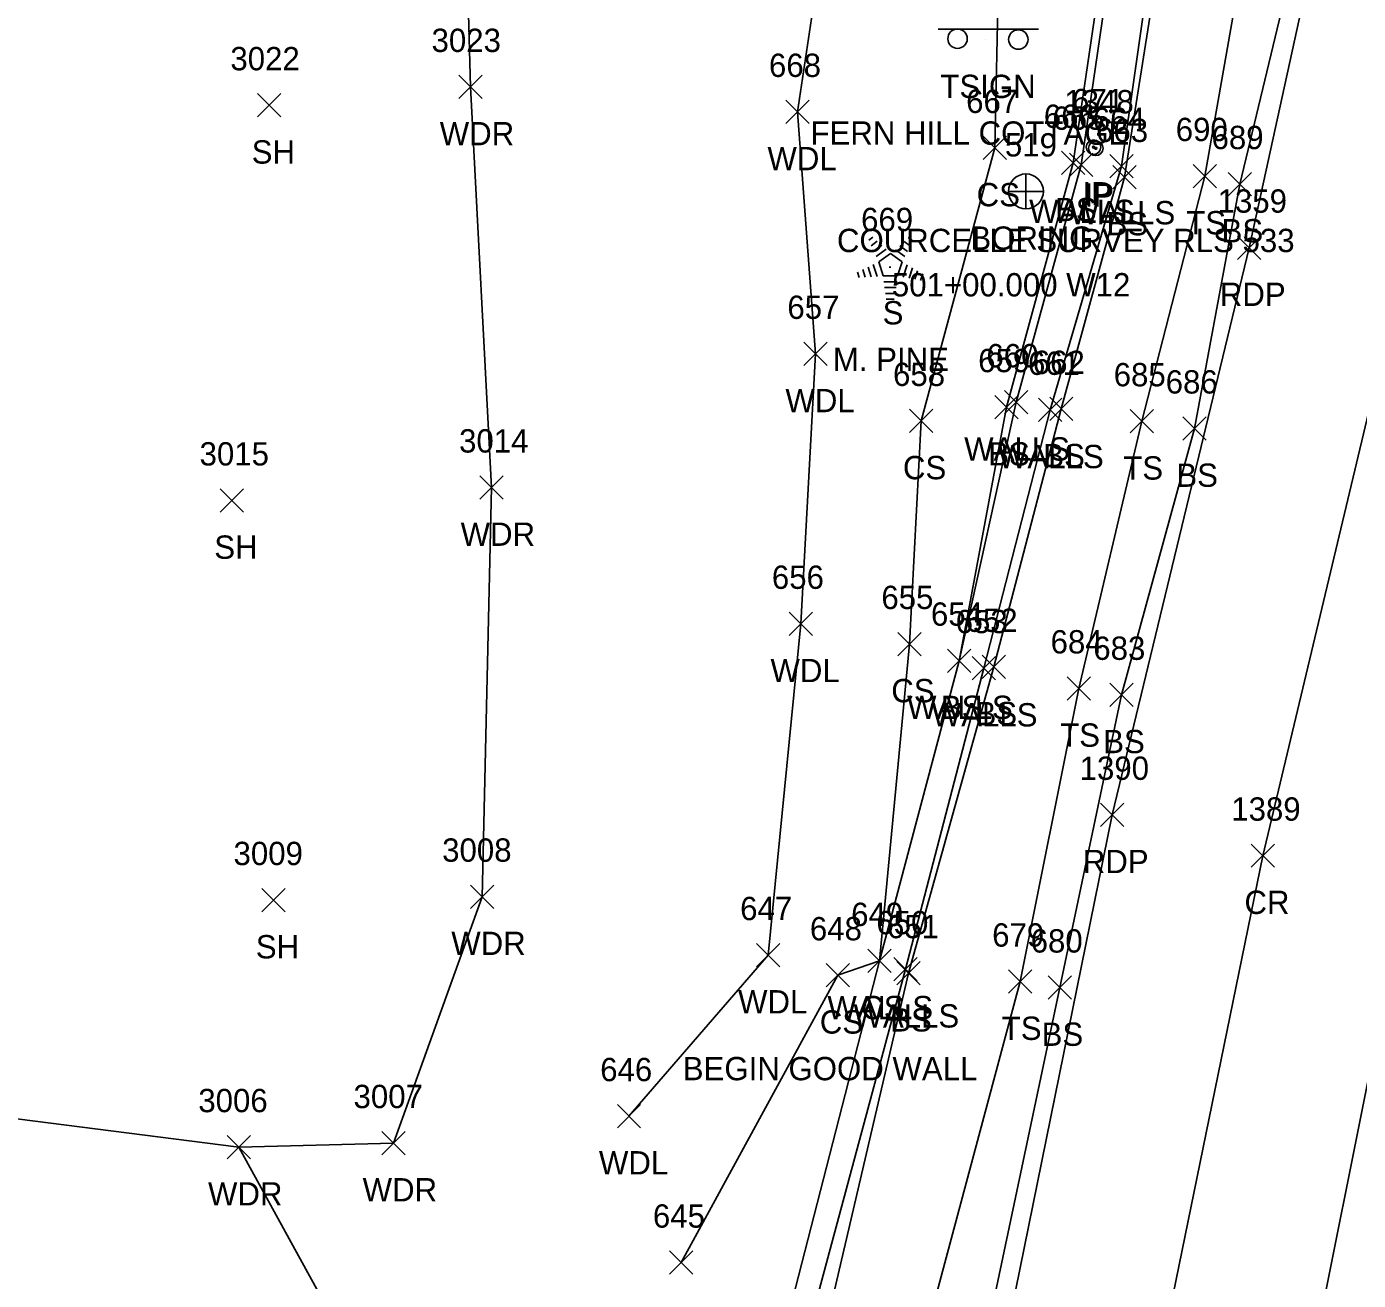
# Model space of a CAD drawing. Extents: x 1509053 to 1511576, y 400838 to 402572.
# Drawn here: x 1509675.3 to 1509789.5, y 401477.9 to 401585.4 of the extents above; entities that cross this region are included whole.
import ezdxf

# ---------------------------------------------------------------- set-up
doc = ezdxf.new("R2010")
doc.units = 0
for name, color, linetype in [('G_A', 7, 'Continuous'), ('G_C', 7, 'Continuous'), ('G_I', 7, 'Continuous'), ('GA_P', 7, 'Continuous'), ('L_A', 7, 'Continuous'), ('L_C', 7, 'Continuous'), ('L_I', 7, 'Continuous'), ('L_TIC', 7, 'Continuous'), ('LAWA', 7, 'Continuous'), ('LELB', 7, 'Continuous'), ('LSOGP', 7, 'Continuous'), ('LTC', 7, 'Continuous'), ('LWS', 7, 'Continuous'), ('M_A', 7, 'Continuous'), ('M_C', 7, 'Continuous'), ('M_I', 7, 'Continuous'), ('MPIR', 7, 'Continuous'), ('P_A', 7, 'Continuous'), ('P_I', 7, 'Continuous'), ('P_TIC', 7, 'Continuous'), ('PET', 7, 'Continuous'), ('PRC', 7, 'Continuous'), ('S_A', 7, 'Continuous'), ('S_C', 7, 'Continuous'), ('SSGN', 7, 'Continuous')]:
    doc.layers.add(name, color=color, linetype=linetype)

msp = doc.modelspace()

# ---------------------------------------------------------------- linework, layer by layer
at = {"layer": 'GA_P'}
for p, q in [((1509760.96, 401571.27), (1509760.96, 401572.77)), ((1509760.96, 401571.27), (1509759.46, 401571.27)), ((1509762.46, 401571.27), (1509760.96, 401571.27)), ((1509760.96, 401569.77), (1509760.96, 401571.27))]:
    msp.add_line(p, q, dxfattribs=at)
for start, end in [(90, 180), (0, 90), (180, 270), (270, 0)]:
    msp.add_arc((1509760.96, 401571.27), 1.5, start, end, dxfattribs=at)
at = {"layer": 'L_TIC'}
for points in [[(1509712.34, 401579.23), (1509714.34, 401581.23)], [(1509714.34, 401579.23), (1509712.34, 401581.23)], [(1509695.09, 401577.66), (1509697.09, 401579.66)], [(1509697.09, 401577.66), (1509695.09, 401579.66)], [(1509740.39, 401577.09), (1509742.39, 401579.09)], [(1509742.39, 401577.09), (1509740.39, 401579.09)], [(1509757.3, 401574), (1509759.3, 401576)], [(1509759.3, 401574), (1509757.3, 401576)], [(1509764.02, 401572.72), (1509766.02, 401574.72)], [(1509766.02, 401572.72), (1509764.02, 401574.72)], [(1509764.7, 401572.56), (1509766.7, 401574.56)], [(1509766.7, 401572.56), (1509764.7, 401574.56)], [(1509768.16, 401572.45), (1509770.16, 401574.45)], [(1509770.16, 401572.45), (1509768.16, 401574.45)], [(1509768.43, 401571.51), (1509770.43, 401573.51)], [(1509770.43, 401571.51), (1509768.43, 401573.51)], [(1509775.3, 401571.59), (1509777.3, 401573.59)], [(1509777.3, 401571.59), (1509775.3, 401573.59)], [(1509778.3, 401570.9), (1509780.3, 401572.9)], [(1509780.3, 401570.9), (1509778.3, 401572.9)], [(1509741.92, 401556.34), (1509743.92, 401558.34)], [(1509743.92, 401556.34), (1509741.92, 401558.34)], [(1509758.29, 401551.77), (1509760.29, 401553.77)], [(1509760.29, 401551.77), (1509758.29, 401553.77)], [(1509759.12, 401552.19), (1509761.12, 401554.19)], [(1509761.12, 401552.19), (1509759.12, 401554.19)], [(1509762.03, 401551.54), (1509764.03, 401553.54)], [(1509764.03, 401551.54), (1509762.03, 401553.54)], [(1509763, 401551.62), (1509765, 401553.62)], [(1509765, 401551.62), (1509763, 401553.62)], [(1509750.98, 401550.59), (1509752.98, 401552.59)], [(1509752.98, 401550.59), (1509750.98, 401552.59)], [(1509769.9, 401550.56), (1509771.9, 401552.56)], [(1509771.9, 401550.56), (1509769.9, 401552.56)], [(1509774.42, 401549.94), (1509776.42, 401551.94)], [(1509776.42, 401549.94), (1509774.42, 401551.94)], [(1509714.13, 401544.88), (1509716.13, 401546.88)], [(1509716.13, 401544.88), (1509714.13, 401546.88)], [(1509691.88, 401543.77), (1509693.88, 401545.77)], [(1509693.88, 401543.77), (1509691.88, 401545.77)], [(1509740.65, 401533.19), (1509742.65, 401535.19)], [(1509742.65, 401533.19), (1509740.65, 401535.19)], [(1509749.98, 401531.46), (1509751.98, 401533.46)], [(1509751.98, 401531.46), (1509749.98, 401533.46)], [(1509754.23, 401530.03), (1509756.23, 401532.03)], [(1509756.23, 401530.03), (1509754.23, 401532.03)], [(1509754.23, 401530.03), (1509756.23, 401532.03)], [(1509756.23, 401530.03), (1509754.23, 401532.03)], [(1509756.35, 401529.39), (1509758.35, 401531.39)], [(1509758.35, 401529.39), (1509756.35, 401531.39)], [(1509757.2, 401529.5), (1509759.2, 401531.5)], [(1509759.2, 401529.5), (1509757.2, 401531.5)], [(1509764.49, 401527.65), (1509766.49, 401529.65)], [(1509766.49, 401527.65), (1509764.49, 401529.65)], [(1509768.15, 401527.1), (1509770.15, 401529.1)], [(1509770.15, 401527.1), (1509768.15, 401529.1)], [(1509695.44, 401509.5), (1509697.44, 401511.5)], [(1509697.44, 401509.5), (1509695.44, 401511.5)], [(1509713.33, 401509.79), (1509715.33, 401511.79)], [(1509715.33, 401509.79), (1509713.33, 401511.79)], [(1509737.87, 401504.78), (1509739.87, 401506.78)], [(1509739.87, 401504.78), (1509737.87, 401506.78)], [(1509747.4, 401504.28), (1509749.4, 401506.28)], [(1509749.4, 401504.28), (1509747.4, 401506.28)], [(1509747.4, 401504.28), (1509749.4, 401506.28)], [(1509749.4, 401504.28), (1509747.4, 401506.28)], [(1509749.64, 401503.57), (1509751.64, 401505.57)], [(1509751.64, 401503.57), (1509749.64, 401505.57)], [(1509743.85, 401503.05), (1509745.85, 401505.05)], [(1509745.85, 401503.05), (1509743.85, 401505.05)], [(1509749.89, 401503.23), (1509751.89, 401505.23)], [(1509751.89, 401503.23), (1509749.89, 401505.23)], [(1509759.48, 401502.51), (1509761.48, 401504.51)], [(1509761.48, 401502.51), (1509759.48, 401504.51)], [(1509762.87, 401502), (1509764.87, 401504)], [(1509764.87, 401502), (1509762.87, 401504)], [(1509725.93, 401490.97), (1509727.93, 401492.97)], [(1509727.93, 401490.97), (1509725.93, 401492.97)], [(1509705.73, 401488.66), (1509707.73, 401490.66)], [(1509707.73, 401488.66), (1509705.73, 401490.66)], [(1509692.47, 401488.31), (1509694.47, 401490.31)], [(1509694.47, 401488.31), (1509692.47, 401490.31)], [(1509730.39, 401478.41), (1509732.39, 401480.41)], [(1509732.39, 401478.41), (1509730.39, 401480.41)]]:
    msp.add_lwpolyline(points, dxfattribs=at)
at = {"layer": 'LAWA'}
for points in [[(1509638.88, 401488.13), (1509666.35, 401492.77), (1509693.47, 401489.31), (1509706.73, 401489.66), (1509714.33, 401510.79), (1509715.13, 401545.88), (1509713.34, 401580.23), (1509712.38, 401615.78), (1509710.87, 401643.63), (1509696.77, 401674.88), (1509690.26, 401693.05), (1509667.45, 401720.56), (1509662.48, 401743.44), (1509649.82, 401764.29), (1509628.65, 401784.18), (1509611.29, 401798.2), (1509592.85, 401815.68), (1509576.11, 401831.25), (1509568.72, 401841.78), (1509569.85, 401855.18), (1509582.24, 401868.06), (1509599.14, 401876.59), (1509619.4, 401883.23)], [(1509726.93, 401491.97), (1509738.87, 401505.78), (1509741.65, 401534.19), (1509742.92, 401557.34), (1509741.39, 401578.09), (1509745.24, 401603.86), (1509743.92, 401621.55), (1509740.79, 401647.31), (1509747.4, 401658.17), (1509733.89, 401672.71)]]:
    msp.add_lwpolyline(points, dxfattribs=at)
at = {"layer": 'LELB'}
for points in [[(1509755.23, 401531.03), (1509759.29, 401552.77), (1509765.02, 401573.72), (1509768.89, 401600.17), (1509768.39, 401615.04), (1509767.46, 401619.69), (1509766.78, 401624.18), (1509765.92, 401630.49), (1509768.74, 401634.34), (1509769.29, 401651.82), (1509765.23, 401681.64), (1509759.03, 401705.77), (1509750.68, 401722.86), (1509752.06, 401726.1), (1509747.7, 401751.42), (1509733.73, 401785.72), (1509720.36, 401816.7), (1509711.77, 401831.6), (1509702.38, 401845.68), (1509682.87, 401874.27), (1509678.54, 401880.58), (1509678.34, 401883.46)], [(1509731.39, 401479.41), (1509744.85, 401504.05), (1509748.4, 401505.28), (1509750.98, 401532.46), (1509751.98, 401551.59), (1509758.3, 401575), (1509758.92, 401604.42), (1509759.53, 401620.15), (1509759.5, 401642.39), (1509763.87, 401657.52), (1509763.43, 401681.67), (1509755.33, 401705.43), (1509747.09, 401724.92), (1509745.86, 401750.35), (1509730.75, 401785.27), (1509718.16, 401815.85), (1509711.77, 401831.6), (1509699.84, 401843.77), (1509676.05, 401879.71), (1509667.99, 401880.98)], [(1509747.77, 401416.63), (1509750.21, 401428.63), (1509752.14, 401443.01), (1509750.46, 401466.15), (1509760.48, 401503.51), (1509765.49, 401528.65), (1509770.9, 401551.56), (1509776.3, 401572.59), (1509780.48, 401596.32), (1509778.93, 401605.73), (1509782.51, 401627.45), (1509784.95, 401662.22), (1509781.8, 401680.58), (1509772.99, 401719.38), (1509769.17, 401721), (1509769.65, 401723.75), (1509771.91, 401724.32), (1509762.66, 401754.93), (1509756.13, 401775.54), (1509751.07, 401789.41), (1509736.27, 401824.32), (1509727.62, 401840.87), (1509712.26, 401861.01), (1509694.01, 401878.11)], [(1509745.54, 401417.2), (1509747.58, 401428.44), (1509752.14, 401443.01), (1509755.83, 401464.96), (1509763.87, 401503), (1509769.15, 401528.1), (1509775.42, 401550.94), (1509779.3, 401571.9), (1509785.18, 401596.41), (1509784.53, 401607.91), (1509782.51, 401627.45), (1509780.91, 401662.72), (1509779.34, 401679.41)], [(1509718.39, 401429.02), (1509722.72, 401429.03), (1509731.91, 401425.72), (1509733.42, 401429.22), (1509734.23, 401430.09), (1509736.1, 401435.75), (1509737.32, 401446.05), (1509750.89, 401504.23), (1509758.2, 401530.5), (1509764, 401552.62), (1509769.43, 401572.51), (1509773.58, 401598.87), (1509773.31, 401621.52)]]:
    msp.add_lwpolyline(points, dxfattribs=at)
at = {"layer": 'LSOGP'}
msp.add_lwpolyline([(1509619.06, 401604.82), (1509615.52, 401571.4), (1509614.57, 401540.12), (1509638.88, 401488.13), (1509666.35, 401492.77), (1509693.47, 401489.31), (1509718.05, 401444.54), (1509718.3, 401438.26), (1509718.5, 401437.3), (1509717.88, 401435.11), (1509718.83, 401433.96), (1509718.39, 401429.02), (1509705.02, 401423.16)], dxfattribs=at)
at = {"layer": 'LTC'}
for p, q in [((1509747.49, 401567.08), (1509747.84, 401567.34)), ((1509747.7, 401566.61), (1509748.22, 401567)), ((1509750.51, 401566.97), (1509751.06, 401566.57)), ((1509750.88, 401567.32), (1509751.3, 401567.01)), ((1509747.9, 401566.15), (1509748.61, 401566.66)), ((1509748.11, 401565.68), (1509748.99, 401566.32)), ((1509748.34, 401565.23), (1509749.35, 401565.96)), ((1509749.35, 401565.96), (1509750.35, 401565.24)), ((1509749.77, 401566.27), (1509750.58, 401565.69)), ((1509750.14, 401566.62), (1509750.82, 401566.13)), ((1509747.43, 401564.79), (1509747.7, 401563.96)), ((1509747.88, 401565.01), (1509748.22, 401563.99)), ((1509748.34, 401565.23), (1509748.73, 401564.03)), ((1509750.35, 401565.24), (1509749.96, 401564.03)), ((1509750.79, 401564.97), (1509750.45, 401563.93)), ((1509751.23, 401564.72), (1509750.94, 401563.83)), ((1509746.52, 401564.36), (1509746.67, 401563.89)), ((1509746.97, 401564.57), (1509747.19, 401563.92)), ((1509749.96, 401564.03), (1509748.73, 401564.03)), ((1509749.92, 401563.53), (1509748.77, 401563.53)), ((1509751.67, 401564.47), (1509751.44, 401563.74)), ((1509752.12, 401564.21), (1509751.93, 401563.64)), ((1509749.83, 401563.03), (1509748.85, 401563.03)), ((1509749.75, 401562.53), (1509748.92, 401562.53)), ((1509749.67, 401562.03), (1509748.99, 401562.03))]:
    msp.add_line(p, q, dxfattribs=at)
at = {"layer": 'LWS'}
for points in [[(1509717.88, 401435.11), (1509721.7, 401433.75), (1509731.54, 401430.25), (1509733.5, 401429.94), (1509734.4, 401435.62), (1509736.9, 401446.54), (1509740.75, 401467.82), (1509750.64, 401504.57), (1509757.35, 401530.39), (1509763.03, 401552.54), (1509769.16, 401573.45), (1509772.81, 401598.99), (1509772.29, 401620.91), (1509769.9, 401620.93), (1509768.93, 401624.44), (1509768.59, 401630.72)], [(1509718.5, 401437.3), (1509722.59, 401436.22), (1509732.01, 401433.32), (1509732.13, 401436.68), (1509733.9, 401446.41), (1509738.81, 401467.91), (1509748.4, 401505.28), (1509755.23, 401531.03), (1509760.12, 401553.19), (1509765.7, 401573.56), (1509769.59, 401600.16), (1509769.79, 401617.16), (1509767.46, 401619.69), (1509767.52, 401624.27), (1509767.18, 401630.52)]]:
    msp.add_lwpolyline(points, dxfattribs=at)
at = {"layer": 'MPIR'}
for centre, radius in [((1509766.76, 401575.07), 0.625), ((1509766.95, 401574.97), 0.625), ((1509766.76, 401575.07), 0.0833), ((1509766.95, 401574.97), 0.0833)]:
    msp.add_circle(centre, radius, dxfattribs=at)
at = {"layer": 'P_TIC'}
for points in [[(1509779.1, 401565.45), (1509781.1, 401567.45)], [(1509781.1, 401565.45), (1509779.1, 401567.45)], [(1509767.35, 401516.81), (1509769.35, 401518.81)], [(1509769.35, 401516.81), (1509767.35, 401518.81)], [(1509780.27, 401513.31), (1509782.27, 401515.31)], [(1509782.27, 401513.31), (1509780.27, 401515.31)]]:
    msp.add_lwpolyline(points, dxfattribs=at)
at = {"layer": 'PET'}
for points in [[(1509690.27, 401895.46), (1509701.64, 401882.87), (1509726.68, 401848.01), (1509747.74, 401803.41), (1509763.81, 401758.01), (1509775.46, 401713.07), (1509786.05, 401661.7), (1509787.8, 401644.85), (1509788.16, 401621.99), (1509786.62, 401596.26), (1509780.1, 401566.45), (1509768.35, 401517.81), (1509758.18, 401467.69), (1509749.79, 401418)], [(1509812.34, 401557.62), (1509800.22, 401536.88), (1509792.46, 401505.8), (1509783.79, 401462.54), (1509775.66, 401414.3), (1509767.41, 401364.72), (1509759.54, 401315.03), (1509750.83, 401266.46)]]:
    msp.add_lwpolyline(points, dxfattribs=at)
at = {"layer": 'PRC'}
for points in [[(1509781.27, 401514.31), (1509792.89, 401562.95)], [(1509781.27, 401514.31), (1509771.28, 401465.39), (1509762.57, 401416.11)]]:
    msp.add_lwpolyline(points, dxfattribs=at)
at = {"layer": 'SSGN'}
for p, q in [((1509753.43, 401585.2), (1509762.03, 401585.2)), ((1509757.46, 401584.3), (1509757.46, 401584.3))]:
    msp.add_line(p, q, dxfattribs=at)
for centre in [(1509755.1, 401584.37), (1509760.31, 401584.3)]:
    msp.add_circle(centre, 0.833, dxfattribs=at)

# ---------------------------------------------------------------- texts
at = {"layer": 'G_A'}
msp.add_text('BORING', height=2, dxfattribs=at).set_placement((1509756.2, 401566.27))
at = {"layer": 'G_C'}
msp.add_text('501+00.000 W12', height=2, dxfattribs=at).set_placement((1509749.47, 401562.27))
at = {"layer": 'G_I'}
msp.add_text('519', height=2, dxfattribs=at).set_placement((1509759.16, 401574.27))
at = {"layer": 'L_A'}
for s, p in [('WDR', (1509710.7, 401575.23)), ('SH', (1509694.58, 401573.66)), ('WDL', (1509738.8, 401573.09)), ('CS', (1509756.74, 401570)), ('WALLS', (1509761.24, 401568.56)), ('BS', (1509763.46, 401568.72)), ('WALLS', (1509764.7, 401568.45)), ('BS', (1509767.87, 401567.51)), ('TS', (1509774.71, 401567.59)), ('BS', (1509777.74, 401566.9)), ('S', (1509748.68, 401559.87)), ('WDL', (1509740.34, 401552.34)), ('WALLS', (1509755.67, 401548.19)), ('BS', (1509757.73, 401547.77)), ('WALLS', (1509758.57, 401547.54)), ('BS', (1509762.45, 401547.62)), ('CS', (1509750.42, 401546.59)), ('TS', (1509769.31, 401546.56)), ('BS', (1509773.86, 401545.94)), ('SH', (1509691.37, 401539.77)), ('WDR', (1509712.49, 401540.88)), ('WDL', (1509739.06, 401529.19)), ('CS', (1509749.42, 401527.46)), ('WALLS', (1509750.77, 401526.03)), ('WALLS', (1509752.89, 401525.39)), ('BS', (1509753.67, 401526.03)), ('BS', (1509756.64, 401525.5)), ('TS', (1509763.9, 401523.65)), ('BS', (1509767.59, 401523.1)), ('WDR', (1509711.69, 401505.79)), ('SH', (1509694.93, 401505.5)), ('WDL', (1509736.28, 401500.78)), ('WALLS', (1509743.94, 401500.28)), ('CS', (1509746.84, 401500.28)), ('CS', (1509743.29, 401499.05)), ('WALLS', (1509746.18, 401499.57)), ('BS', (1509749.33, 401499.23)), ('TS', (1509758.89, 401498.51)), ('BS', (1509762.31, 401498)), ('WDL', (1509724.35, 401486.97)), ('WDR', (1509690.83, 401484.31)), ('WDR', (1509704.09, 401484.66))]:
    msp.add_text(s, height=2, dxfattribs=at).set_placement(p)
at = {"layer": 'L_C'}
for s, p in [('M. PINE', (1509744.41, 401555.87)), ('BEGIN GOOD WALL', (1509731.54, 401495.05))]:
    msp.add_text(s, height=2, dxfattribs=at).set_placement(p)
at = {"layer": 'L_I'}
for s, p in [('3023', (1509710, 401583.23)), ('3022', (1509692.75, 401581.66)), ('668', (1509738.93, 401581.09)), ('667', (1509755.84, 401578)), ('666', (1509762.5, 401576.72)), ('665', (1509763.24, 401576.56)), ('664', (1509766.7, 401576.45)), ('663', (1509766.98, 401575.51)), ('690', (1509773.81, 401575.59)), ('689', (1509776.88, 401574.9)), ('669', (1509746.83, 401567.87)), ('657', (1509740.51, 401560.34)), ('659', (1509756.87, 401555.77)), ('660', (1509757.58, 401556.19)), ('661', (1509761.14, 401555.54)), ('662', (1509761.55, 401555.62)), ('658', (1509749.57, 401554.59)), ('685', (1509768.49, 401554.56)), ('686', (1509772.95, 401553.94)), ('3015', (1509690.11, 401547.77)), ('3014', (1509712.36, 401548.88)), ('656', (1509739.18, 401537.19)), ('655', (1509748.57, 401535.46)), ('654', (1509752.82, 401534.03)), ('654', (1509752.82, 401534.03)), ('653', (1509754.94, 401533.39)), ('652', (1509755.79, 401533.5)), ('684', (1509763.08, 401531.65)), ('683', (1509766.74, 401531.1)), ('3009', (1509693.02, 401513.5)), ('3008', (1509710.91, 401513.79)), ('647', (1509736.46, 401508.78)), ('649', (1509745.98, 401508.28)), ('649', (1509745.98, 401508.28)), ('648', (1509742.44, 401507.05)), ('650', (1509748.14, 401507.57)), ('651', (1509749.05, 401507.23)), ('679', (1509758.07, 401506.51)), ('680', (1509761.37, 401506)), ('646', (1509724.46, 401494.97)), ('3006', (1509690, 401492.31)), ('3007', (1509703.31, 401492.66)), ('645', (1509728.98, 401482.41))]:
    msp.add_text(s, height=2, dxfattribs=at).set_placement(p)
at = {"layer": 'LTC'}
msp.add_text('.', height=1.04, rotation=270, dxfattribs=at).set_placement((1509749.23, 401564.97))
at = {"layer": 'M_A'}
for p in [(1509765.81, 401570.07), (1509766, 401569.97)]:
    msp.add_text('IP', height=2, dxfattribs=at).set_placement(p)
at = {"layer": 'M_C'}
msp.add_text('COURCELLE SURVEY RLS 533', height=2, dxfattribs=at).set_placement((1509744.76, 401566.07))
at = {"layer": 'M_I'}
for s, p in [('1348', (1509764.26, 401577.97)), ('671', (1509764.92, 401578.07))]:
    msp.add_text(s, height=2, dxfattribs=at).set_placement(p)
at = {"layer": 'P_A'}
for s, p in [('RDP', (1509777.59, 401561.45)), ('RDP', (1509765.84, 401512.81)), ('CR', (1509779.7, 401509.31))]:
    msp.add_text(s, height=2, dxfattribs=at).set_placement(p)
at = {"layer": 'P_I'}
for s, p in [('1359', (1509777.4, 401569.45)), ('1390', (1509765.57, 401520.81)), ('1389', (1509778.57, 401517.31))]:
    msp.add_text(s, height=2, dxfattribs=at).set_placement(p)
at = {"layer": 'S_A'}
msp.add_text('TSIGN', height=2, dxfattribs=at).set_placement((1509753.63, 401579.28))
at = {"layer": 'S_C'}
msp.add_text('FERN HILL COTTAGE', height=2, dxfattribs=at).set_placement((1509742.49, 401575.28))

doc.saveas('drawing.dxf')
